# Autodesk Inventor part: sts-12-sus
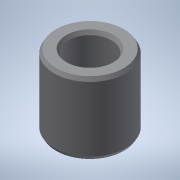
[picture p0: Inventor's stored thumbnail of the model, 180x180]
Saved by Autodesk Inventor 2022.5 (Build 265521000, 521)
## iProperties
Created: 2016-12
Part Number: sts-12-sus
Material: 一般
Document SubType Name: Modeling
Designer: imaocorp
Density: 1 g/cm^3
Appearance: 既定
Author: imaocorp
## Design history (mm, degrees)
node "sts-12-sus.x_t1"
node "sts-12-sus"
node "Base1"
